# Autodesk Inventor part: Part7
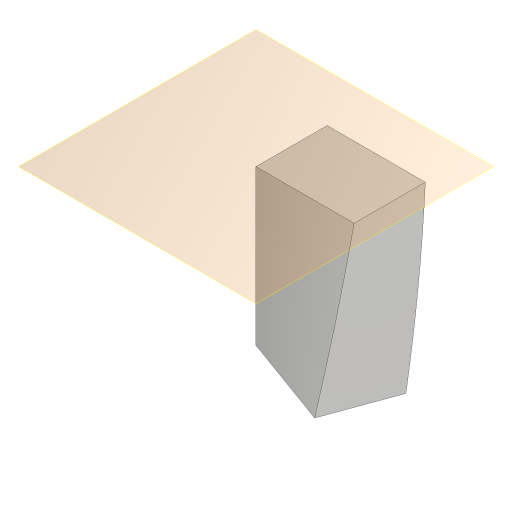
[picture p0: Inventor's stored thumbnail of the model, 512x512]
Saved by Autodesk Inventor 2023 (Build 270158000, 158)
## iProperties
Created: 2015-07
Part Number: Part7
Material: Generic
Document SubType Name: Modeling
Designer: Sandeep
Density: 1 g/cm^3
Appearance: Default
Author: Sandeep
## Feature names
1. Sweep1
## Parameters: d0 = 0, d1 = 20 deg
